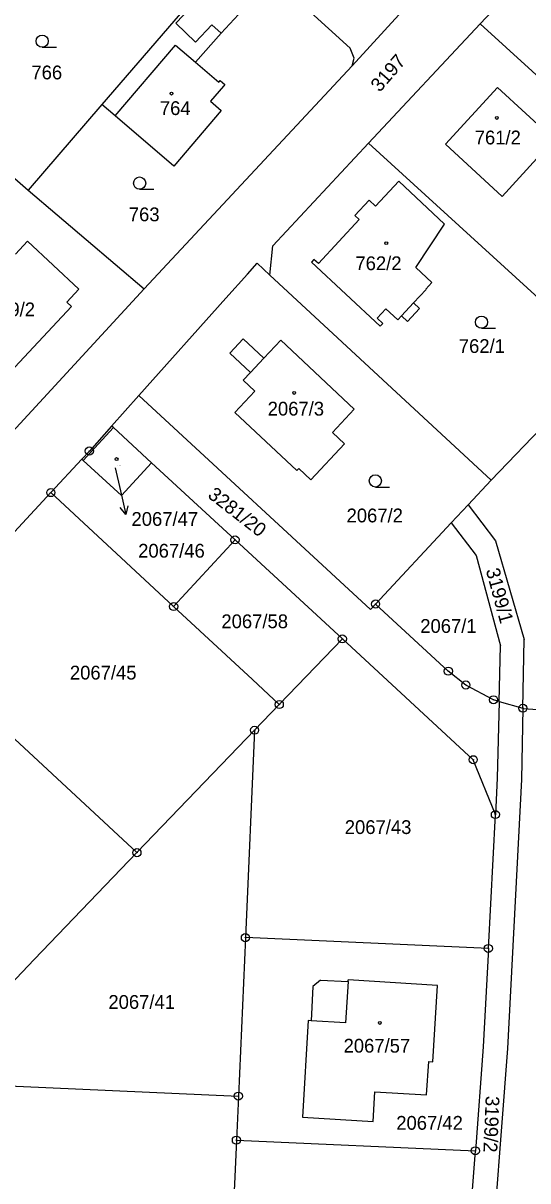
# Model space of a CAD drawing. Extents: x -736345 to -729997, y -1130177 to -1122501.
# Drawn here: x -733025.5 to -732963.2, y -1128105.2 to -1127962.5 of the extents above; entities that cross this region are included whole.
import ezdxf

# ---------------------------------------------------------------- set-up
doc = ezdxf.new("R2010")
doc.units = 0
for name, color, linetype in [('Vrstva 1', 7, 'Continuous'), ('Vrstva 16', 7, 'Continuous'), ('Vrstva 18', 7, 'Continuous'), ('Vrstva 19', 7, 'Continuous'), ('Vrstva 25', 7, 'Continuous'), ('Vrstva 4', 7, 'Continuous')]:
    doc.layers.add(name, color=color, linetype=linetype)

msp = doc.modelspace()

# ---------------------------------------------------------------- linework, layer by layer
at = {"layer": 'Vrstva 1'}
for points in [[(-732969.11, -1127962.53), (-732955.24, -1127947.91)], [(-732985.14, -1127965.53), (-732998.97, -1127952.96)], [(-733002.47, -1127957.03), (-733015.77, -1127972.49)], [(-732998.4, -1127960.83), (-733001.07, -1127963.69)], [(-732984.91, -1127967.72), (-732978.69, -1127960.93)], [(-733001.07, -1127963.69), (-733004.23, -1127967.28)], [(-732969.11, -1127962.53), (-732982.87, -1127977.25)], [(-732939.78, -1127989.21), (-732969.11, -1127962.53)], [(-732984.65, -1127966.78), (-732985.14, -1127965.53)], [(-732984.91, -1127967.72), (-733010.54, -1127995.24)], [(-733004.23, -1127967.28), (-733001.33, -1127969.74)], [(-732984.91, -1127967.72), (-732984.65, -1127966.78)], [(-733001.33, -1127969.74), (-733001.17, -1127969.55)], [(-733001.17, -1127969.55), (-733000.59, -1127970.04)], [(-733000.76, -1127970.23), (-733002.39, -1127972.08)], [(-733000.59, -1127970.04), (-733000.76, -1127970.23)], [(-732973.39, -1127977.4), (-732966.97, -1127970.4)], [(-732966.97, -1127970.4), (-732959.97, -1127976.82)], [(-733002.39, -1127972.08), (-733001.06, -1127973.25)], [(-733015.77, -1127972.49), (-733024.87, -1127983.07)], [(-733014.12, -1127973.9), (-733015.77, -1127972.49)], [(-733001.06, -1127973.25), (-733006.91, -1127980.08)], [(-733006.91, -1127980.08), (-733014.12, -1127973.9)], [(-732982.87, -1127977.25), (-732994.7, -1127989.91)], [(-732982.87, -1127977.25), (-732953.54, -1128004.02)], [(-732966.39, -1127983.82), (-732973.39, -1127977.4)], [(-732959.97, -1127976.82), (-732966.39, -1127983.82)], [(-733028.53, -1127979.88), (-733024.87, -1127983.07)], [(-732979.16, -1127981.94), (-732982.02, -1127985.01)], [(-732979.16, -1127981.94), (-732973.49, -1127987.26)], [(-733024.87, -1127983.07), (-733010.54, -1127995.24)], [(-732982.81, -1127984.29), (-732984.57, -1127986.17)], [(-732982.02, -1127985.01), (-732982.81, -1127984.29)], [(-732984.02, -1127986.68), (-732989.07, -1127992.11)], [(-732984.57, -1127986.17), (-732984.02, -1127986.68)], [(-732977.06, -1127992.61), (-732973.49, -1127987.26)], [(-733024.94, -1127989.36), (-733026.43, -1127990.96)], [(-733018.62, -1127995.26), (-733024.94, -1127989.36)], [(-732995.04, -1127993.53), (-732994.7, -1127989.91)], [(-732997.83, -1127993.41), (-732996.63, -1127992.06)], [(-732996.63, -1127992.06), (-732995.04, -1127993.53)], [(-732989.62, -1127991.6), (-732989.93, -1127991.93)], [(-732989.93, -1127991.93), (-732981.44, -1127999.84)], [(-732989.07, -1127992.11), (-732989.62, -1127991.6)], [(-733000.49, -1127996.39), (-732997.83, -1127993.41)], [(-732967.74, -1128018.8), (-732995.04, -1127993.53)], [(-732975.08, -1127994.45), (-732977.06, -1127992.61)], [(-733010.54, -1127995.24), (-733037.37, -1128024.3)], [(-733020.11, -1127996.86), (-733018.62, -1127995.26)], [(-732975.83, -1127995.25), (-732975.08, -1127994.45)], [(-732975.78, -1127995.3), (-732975.83, -1127995.25)], [(-733011.2, -1128008.38), (-733000.49, -1127996.39)], [(-732977.33, -1127996.96), (-732975.78, -1127995.3)], [(-733027.71, -1128006.14), (-733019.54, -1127997.39)], [(-733019.54, -1127997.39), (-733020.11, -1127996.86)], [(-732981.82, -1127998.85), (-732980.73, -1127997.68)], [(-732980.73, -1127997.68), (-732979.26, -1127999.04)], [(-732978.09, -1127999.25), (-732976.59, -1127997.64)], [(-732976.59, -1127997.64), (-732977.33, -1127996.96)], [(-732981.12, -1127999.49), (-732981.82, -1127998.85)], [(-732981.44, -1127999.84), (-732981.12, -1127999.49)], [(-732979.26, -1127999.04), (-732978.83, -1127998.57)], [(-732978.83, -1127998.57), (-732978.09, -1127999.25)], [(-732998.35, -1128001.39), (-733000, -1128003.14)], [(-732995.8, -1128003.79), (-732998.35, -1128001.39)], [(-732993.7, -1128001.56), (-732995.8, -1128003.79)], [(-732984.65, -1128010.06), (-732993.7, -1128001.56)], [(-733000, -1128003.14), (-732997.44, -1128005.54)], [(-732967.74, -1128018.8), (-732953.54, -1128004.02)], [(-732997.44, -1128005.54), (-732998.33, -1128006.48)], [(-732998.33, -1128006.48), (-732996.89, -1128007.84)], [(-732996.89, -1128007.84), (-732999.36, -1128010.46)], [(-733011.2, -1128008.38), (-733014.57, -1128012.14)], [(-732982.65, -1128034.78), (-733011.2, -1128008.38)], [(-732999.36, -1128010.46), (-732991.74, -1128017.62)], [(-732987.34, -1128012.94), (-732984.65, -1128010.06)], [(-733014.57, -1128012.14), (-733017.32, -1128015.22)], [(-733014.35, -1128012.34), (-733014.57, -1128012.14)], [(-733009.64, -1128016.69), (-733014.35, -1128012.34)], [(-732985.84, -1128014.34), (-732987.34, -1128012.94)], [(-733017.32, -1128015.22), (-733018.25, -1128016.22)], [(-732990, -1128018.76), (-732985.84, -1128014.34)], [(-733018.25, -1128016.22), (-733022.08, -1128020.35)], [(-733018.25, -1128016.22), (-733018.07, -1128016.38)], [(-733018.07, -1128016.38), (-733013.37, -1128020.71)], [(-733013.37, -1128020.71), (-733009.64, -1128016.69)], [(-732999.35, -1128026.18), (-733009.64, -1128016.69)], [(-732991.74, -1128017.62), (-732991.49, -1128017.36)], [(-732991.49, -1128017.36), (-732990, -1128018.76)], [(-732970.6, -1128021.87), (-732967.74, -1128018.8)], [(-733022.08, -1128020.35), (-733034.06, -1128033.28)], [(-733022.08, -1128020.35), (-733009.88, -1128031.66)], [(-732972.68, -1128024.09), (-732970.6, -1128021.87)], [(-732970.6, -1128021.87), (-732967.22, -1128026.3)], [(-732982.01, -1128034.09), (-732972.68, -1128024.09)], [(-732972.68, -1128024.09), (-732969.6, -1128028.12)], [(-733006.92, -1128034.4), (-732999.35, -1128026.18)], [(-732986.11, -1128038.39), (-732999.35, -1128026.18)], [(-732967.22, -1128026.3), (-732963.69, -1128038.45)], [(-732969.6, -1128028.12), (-732966.58, -1128039.23)], [(-733009.88, -1128031.66), (-733006.92, -1128034.4)], [(-733006.92, -1128034.4), (-732997.2, -1128043.41)], [(-732982.65, -1128034.78), (-732982.01, -1128034.09)], [(-732973.04, -1128042.37), (-732982.01, -1128034.09)], [(-733039.3, -1128038.93), (-733011.45, -1128064.75)], [(-732986.11, -1128038.39), (-732993.89, -1128046.48)], [(-732969.96, -1128053.29), (-732986.11, -1128038.39)], [(-732966.76, -1128046.1), (-732966.58, -1128039.23)], [(-732963.84, -1128046.94), (-732963.69, -1128038.45)], [(-732970.87, -1128044.08), (-732973.04, -1128042.37)], [(-732997.2, -1128043.41), (-732993.89, -1128046.48)], [(-732967.46, -1128045.9), (-732970.87, -1128044.08)], [(-732993.89, -1128046.48), (-732996.94, -1128049.65)], [(-732966.76, -1128046.1), (-732967.46, -1128045.9)], [(-732966.76, -1128046.1), (-732967, -1128055.56)], [(-732966.76, -1128046.1), (-732963.84, -1128046.94)], [(-732963.84, -1128046.94), (-732964, -1128055.71)], [(-732963.74, -1128046.97), (-732963.84, -1128046.94)], [(-732963.74, -1128046.97), (-732959.89, -1128047.25)], [(-732998.95, -1128051.74), (-732996.94, -1128049.65)], [(-732996.94, -1128049.65), (-732998.07, -1128075.23)], [(-733011.45, -1128064.75), (-732998.95, -1128051.74)], [(-732967.23, -1128060.05), (-732969.96, -1128053.29)], [(-732967, -1128055.56), (-732967.23, -1128060.05)], [(-732964, -1128055.71), (-732965.74, -1128088.91)], [(-732968.1, -1128076.56), (-732967.23, -1128060.05)], [(-733024.12, -1128077.94), (-733011.45, -1128064.75)], [(-732998.07, -1128075.23), (-732998.94, -1128094.77)], [(-732968.1, -1128076.56), (-732998.07, -1128075.23)], [(-732968.1, -1128076.56), (-732968.73, -1128088.68)], [(-733029.37, -1128083.41), (-733024.12, -1128077.94)], [(-732988.82, -1128080.49), (-732989.75, -1128081.27), (-732989.94, -1128085.48)], [(-732988.82, -1128080.49), (-732985.41, -1128080.62)], [(-732985.41, -1128080.62), (-732985.41, -1128080.45)], [(-732974.94, -1128090.55), (-732974.37, -1128081.13), (-732985.41, -1128080.45)], [(-732990.31, -1128085.45), (-732991.03, -1128097.37), (-732982.31, -1128097.89), (-732982.12, -1128094.23), (-732975.74, -1128094.62), (-732975.43, -1128090.51), (-732974.94, -1128090.55)], [(-732989.94, -1128085.48), (-732990.31, -1128085.45)], [(-732968.73, -1128088.68), (-732969.7, -1128101.51)], [(-732965.74, -1128088.91), (-732967.98, -1128118.4)], [(-733030.04, -1128093.39), (-732998.94, -1128094.77)], [(-732998.94, -1128094.77), (-732999.18, -1128100.2)], [(-732999.18, -1128100.2), (-733000.14, -1128121.73)], [(-732999.18, -1128100.2), (-732969.7, -1128101.51)], [(-732970.96, -1128118.07), (-732969.7, -1128101.51)]]:
    msp.add_lwpolyline(points, dxfattribs=at)
at = {"layer": 'Vrstva 16'}
msp.add_lwpolyline([(-733014.12, -1128017.28), (-733013.48, -1128020.12)], dxfattribs=at)
at = {"layer": 'Vrstva 25'}
for points in [[(-733023.14, -1127965.44), (-733021.39, -1127965.44)], [(-733011.12, -1127982.93), (-733009.37, -1127982.93)], [(-732968.95, -1128000.08), (-732967.2, -1128000.08)], [(-733013.48, -1128020.12), (-733012.821, -1128023.046)], [(-732982.04, -1128019.66), (-732980.29, -1128019.66)], [(-733012.553, -1128021.961), (-733012.821, -1128023.046), (-733013.528, -1128022.18)]]:
    msp.add_lwpolyline(points, dxfattribs=at)
for centre, radius in [((-733023.14, -1127964.69), 0.75), ((-733007.19, -1127971.15), 0.175), ((-732967.05, -1127974.15), 0.175), ((-733011.12, -1127982.18), 0.75), ((-732980.69, -1127989.59), 0.175), ((-732968.95, -1127999.33), 0.75), ((-732992.05, -1128008.06), 0.175), ((-733017.32, -1128015.22), 0.5), ((-733017.32, -1128015.22), 0.032), ((-733013.96, -1128016.21), 0.175), ((-732982.04, -1128018.91), 0.75), ((-733022.08, -1128020.35), 0.5), ((-733022.08, -1128020.35), 0.032), ((-732999.35, -1128026.18), 0.5), ((-732999.35, -1128026.18), 0.032), ((-732982.01, -1128034.09), 0.5), ((-733006.92, -1128034.4), 0.5), ((-733006.92, -1128034.4), 0.032), ((-732982.01, -1128034.09), 0.032), ((-732986.11, -1128038.39), 0.5), ((-732986.11, -1128038.39), 0.032), ((-732973.04, -1128042.37), 0.5), ((-732973.04, -1128042.37), 0.032), ((-732970.87, -1128044.08), 0.5), ((-732970.87, -1128044.08), 0.032), ((-732993.89, -1128046.48), 0.5), ((-732993.89, -1128046.48), 0.032), ((-732967.46, -1128045.9), 0.5), ((-732967.46, -1128045.9), 0.032), ((-732963.84, -1128046.94), 0.5), ((-732963.84, -1128046.94), 0.032), ((-732996.94, -1128049.65), 0.5), ((-732996.94, -1128049.65), 0.032), ((-732969.96, -1128053.29), 0.5), ((-732969.96, -1128053.29), 0.032), ((-732967.23, -1128060.05), 0.5), ((-732967.23, -1128060.05), 0.032), ((-733011.45, -1128064.75), 0.5), ((-733011.45, -1128064.75), 0.032), ((-732998.07, -1128075.23), 0.5), ((-732998.07, -1128075.23), 0.032), ((-732968.1, -1128076.56), 0.5), ((-732968.1, -1128076.56), 0.032), ((-732981.48, -1128085.75), 0.175), ((-732998.94, -1128094.77), 0.5), ((-732998.94, -1128094.77), 0.032), ((-732999.18, -1128100.2), 0.5), ((-732999.18, -1128100.2), 0.032), ((-732969.7, -1128101.51), 0.5), ((-732969.7, -1128101.51), 0.032)]:
    msp.add_circle(centre, radius, dxfattribs=at)
at = {"layer": 'Vrstva 4'}
for points in [[(-733001.96, -1127957.51), (-733006.67, -1127962.48)], [(-733006.67, -1127962.48), (-733004.21, -1127964.82)], [(-733004.21, -1127964.82), (-733002.19, -1127962.65)], [(-733002.19, -1127962.65), (-733001.07, -1127963.69)], [(-733014.12, -1127973.9), (-733006.7, -1127965.17)], [(-733006.7, -1127965.17), (-733004.23, -1127967.28)], [(-732978.83, -1127998.57), (-732977.33, -1127996.96)], [(-732997.44, -1128005.54), (-732995.8, -1128003.79)], [(-733014.35, -1128012.34), (-733018.07, -1128016.38)], [(-732985.41, -1128080.62), (-732985.73, -1128085.75), (-732989.94, -1128085.48)]]:
    msp.add_lwpolyline(points, dxfattribs=at)

# ---------------------------------------------------------------- texts
at = {"layer": 'Vrstva 16'}
msp.add_text('2067/47', height=1.7, dxfattribs=at).set_placement((-733012.12, -1128024.45))
at = {"layer": 'Vrstva 18'}
for s, rotation, p in [('3197', 49.10039, (-732981.49, -1127971.058)), ('3281/20', 322.10256, (-733002.83, -1128020.866)), ('3199/1', 285.20227, (-732968.425, -1128029.91)), ('3199/2', 267.60213, (-732968.419, -1128094.728))]:
    msp.add_text(s, height=1.7, rotation=rotation, dxfattribs=at).set_placement(p)
for s, p in [('766', (-733024.47, -1127969.39)), ('763', (-733012.45, -1127986.89)), ('762/1', (-732971.74, -1128003.13)), ('2067/2', (-732985.59, -1128024.02)), ('2067/46', (-733011.3, -1128028.37)), ('2067/58', (-733001.03, -1128037.07)), ('2067/1', (-732976.5, -1128037.65)), ('2067/45', (-733019.72, -1128043.4)), ('2067/43', (-732985.81, -1128062.45)), ('2067/41', (-733014.97, -1128084.01)), ('2067/42', (-732979.46, -1128098.92))]:
    msp.add_text(s, height=1.7, dxfattribs=at).set_placement(p)
at = {"layer": 'Vrstva 19'}
for s, height, p in [('764', 1.7, (-733008.62, -1127973.79)), ('761/2', 1.7, (-732969.78, -1127977.41)), ('762/2', 1.7, (-732984.5, -1127992.92)), ('789/2', 1.7, (-733029.71, -1127998.61)), ('2067/3', 1.7, (-732995.32, -1128010.85)), ('2067/47', 0.1, (-733013.92, -1128017.08)), ('2067/57', 1.7, (-732985.958, -1128089.41))]:
    msp.add_text(s, height=height, dxfattribs=at).set_placement(p)

doc.saveas('drawing.dxf')
